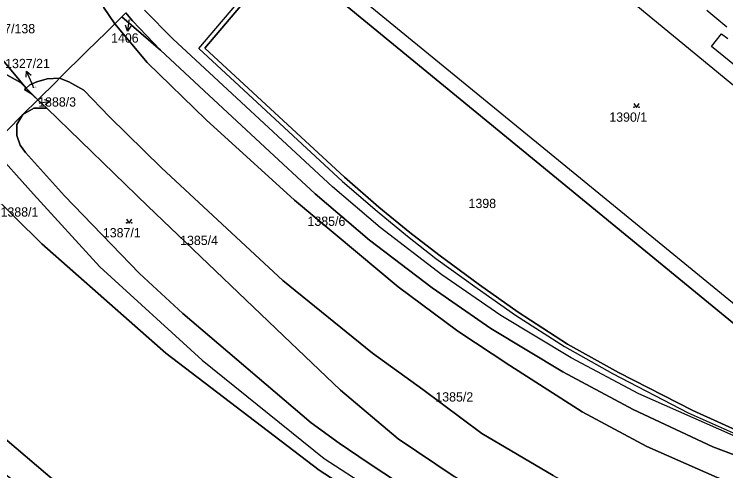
# Model space of a CAD drawing. Extents: x -598934 to -598196, y -1162208 to -1161502.
# Drawn here: x -598686.2 to -598555.4, y -1161981.4 to -1161897.6 of the extents above; entities that cross this region are included whole.
import ezdxf

# ---------------------------------------------------------------- set-up
doc = ezdxf.new("R2010")
doc.units = 0
for name, color, linetype in [('KN_CAR_KR', 7, 'Continuous'), ('KN_KULTURY', 7, 'Continuous'), ('KN_PARC_CIS_POM', 7, 'Continuous'), ('KN_PARC_CIS_POZ', 7, 'Continuous'), ('KN_PARC_PLOCHA', 7, 'Continuous'), ('PARC_C_SIPKA', 7, 'Continuous'), ('parcely_l', 7, 'Continuous')]:
    doc.layers.add(name, color=color, linetype=linetype)

msp = doc.modelspace()

# ---------------------------------------------------------------- linework, layer by layer
at = {"layer": 'KN_CAR_KR'}
for points in [[(-598516.72, -1161941.32), (-598602.99, -1161870.34)], [(-598652.25, -1161903.88), (-598637.61, -1161886.65)], [(-598623.15, -1161894.09), (-598537.06, -1161964.54)], [(-598662.28, -1161896.84), (-598657.06, -1161902.15)], [(-598558.92, -1161896.88), (-598555.23, -1161899.93)], [(-598627.73, -1161929.3), (-598657.06, -1161902.15)], [(-598558.05, -1161903.51), (-598556.19, -1161901.18)], [(-598556.19, -1161901.18), (-598555.07, -1161902.03)], [(-598652.25, -1161903.88), (-598625.88, -1161928.3)], [(-598546.38, -1161912.99), (-598558.05, -1161903.51)], [(-598684, -1161911.17), (-598681.87, -1161913.33)], [(-598682.64, -1161930.66), (-598690.51, -1161921.94)], [(-598625.88, -1161928.3), (-598619.52, -1161933.78)], [(-598618.92, -1161936.73), (-598627.73, -1161929.3)], [(-598682.64, -1161930.66), (-598670.43, -1161944)], [(-598619.52, -1161933.78), (-598613.94, -1161938.33)], [(-598607.61, -1161945.47), (-598618.92, -1161936.73)], [(-598613.94, -1161938.33), (-598608.69, -1161942.42)], [(-598608.69, -1161942.42), (-598601.14, -1161947.88)], [(-598670.43, -1161944), (-598651.65, -1161961.13)], [(-598596.74, -1161952.91), (-598607.61, -1161945.47)], [(-598601.14, -1161947.88), (-598594.08, -1161952.86)], [(-598583.86, -1161960.67), (-598596.74, -1161952.91)], [(-598594.08, -1161952.86), (-598585.08, -1161958.62)], [(-598585.08, -1161958.62), (-598576.24, -1161963.59)], [(-598571.39, -1161967.31), (-598583.86, -1161960.67)], [(-598651.65, -1161961.13), (-598629.22, -1161979.16)], [(-598576.24, -1161963.59), (-598562.32, -1161970.77)], [(-598546.7, -1161978.17), (-598571.39, -1161967.31)], [(-598562.32, -1161970.77), (-598547.47, -1161977.42)], [(-598629.22, -1161979.16), (-598612.23, -1161990.21)]]:
    msp.add_lwpolyline(points, dxfattribs=at)
at = {"layer": 'KN_KULTURY'}
for points in [[(-598572.33, -1161913.97), (-598571.83, -1161914.72), (-598571.33, -1161913.97)], [(-598665.55, -1161935.2), (-598665.05, -1161935.95), (-598664.55, -1161935.2)]]:
    msp.add_lwpolyline(points, dxfattribs=at)
for centre in [(-598572.28, -1161914.67), (-598571.38, -1161914.67), (-598665.5, -1161935.9), (-598664.6, -1161935.9)]:
    msp.add_circle(centre, 0.05, dxfattribs=at)
at = {"layer": 'KN_PARC_PLOCHA'}
for points in [[(-598670.57, -1161893.33), (-598669.8, -1161896.31), (-598667.72, -1161899.35), (-598669.24, -1161900.87), (-598672.85, -1161904.41), (-598677.88, -1161909.36), (-598680.13, -1161909.46), (-598682.02, -1161909.99), (-598683.3, -1161910.59), (-598684, -1161911.17), (-598695.16, -1161897.89), (-598688.82, -1161889.68), (-598683.43, -1161882.7)], [(-598538.52, -1161967.05), (-598636.59, -1161886.64), (-598637.04, -1161887.15), (-598651.19, -1161903.86), (-598625.52, -1161927.53), (-598619.21, -1161933), (-598613.47, -1161937.67), (-598608.15, -1161941.8), (-598600.71, -1161947.3), (-598593.56, -1161952.32), (-598584.52, -1161958.15), (-598575.16, -1161963.39), (-598561.46, -1161970.35), (-598547.04, -1161976.92)], [(-598538.52, -1161967.05), (-598547.04, -1161976.92), (-598561.46, -1161970.35), (-598575.16, -1161963.39), (-598584.52, -1161958.15), (-598593.56, -1161952.32), (-598600.71, -1161947.3), (-598608.15, -1161941.8), (-598613.47, -1161937.67), (-598619.21, -1161933), (-598625.52, -1161927.53), (-598651.19, -1161903.86), (-598637.04, -1161887.15), (-598636.59, -1161886.64)], [(-598684, -1161911.17), (-598685.05, -1161910.11), (-598687.53, -1161908.7), (-598689.32, -1161908.13), (-598691.38, -1161907.92), (-598693.18, -1161908.07), (-598695.22, -1161908.62), (-598696.83, -1161909.36), (-598699, -1161911.05), (-598700.66, -1161912.89), (-598702.8, -1161915.85), (-598703.84, -1161917.32), (-598707.37, -1161913.69), (-598695.16, -1161897.89)], [(-598659.32, -1161904.21), (-598666.41, -1161898.08), (-598665.71, -1161897.32), (-598664.45, -1161898.81)], [(-598684, -1161911.17), (-598684.33, -1161911.44), (-598683.21, -1161912.1), (-598681.87, -1161913.33), (-598684.58, -1161916.02), (-598690.51, -1161921.94), (-598695.11, -1161917.58), (-598694.89, -1161917.09), (-598696.49, -1161916.92), (-598697.85, -1161917.15), (-598699.11, -1161917.76), (-598700.12, -1161918.59), (-598701.26, -1161919.92), (-598703.84, -1161917.32), (-598702.8, -1161915.85), (-598700.66, -1161912.89), (-598699, -1161911.05), (-598696.83, -1161909.36), (-598695.22, -1161908.62), (-598693.18, -1161908.07), (-598691.38, -1161907.92), (-598689.32, -1161908.13), (-598687.53, -1161908.7), (-598685.05, -1161910.11)], [(-598681.87, -1161913.33), (-598683.21, -1161912.1), (-598684.33, -1161911.44), (-598684, -1161911.17), (-598683.3, -1161910.59), (-598682.02, -1161909.99), (-598680.13, -1161909.46), (-598677.88, -1161909.36), (-598678.45, -1161909.95)], [(-598680.2, -1161914.85), (-598682.56, -1161914.86), (-598684.58, -1161916.02), (-598681.87, -1161913.33)]]:
    msp.add_lwpolyline(points, close=True, dxfattribs=at)
for points in [[(-598665.71, -1161897.32), (-598666.41, -1161898.08), (-598667.72, -1161899.35), (-598669.8, -1161896.31)], [(-598544.66, -1161987.36), (-598557.04, -1161982.63), (-598569.93, -1161976.98), (-598581.81, -1161970.58), (-598595.12, -1161962.11), (-598604.67, -1161955.82), (-598615.63, -1161947.65), (-598634.7, -1161931.71), (-598650.91, -1161917.02), (-598661.77, -1161906.44), (-598667.72, -1161899.35), (-598666.41, -1161898.08), (-598659.32, -1161904.21), (-598650.45, -1161912.46), (-598640.12, -1161922.02), (-598630.86, -1161930.55), (-598620.88, -1161939.07), (-598609.4, -1161947.85), (-598598.62, -1161955.32), (-598585.4, -1161963.26), (-598572.47, -1161970.15), (-598557.82, -1161977.02), (-598546.22, -1161981.39)], [(-598546.22, -1161981.39), (-598557.82, -1161977.02), (-598572.47, -1161970.15), (-598585.4, -1161963.26), (-598598.62, -1161955.32), (-598609.4, -1161947.85), (-598620.88, -1161939.07), (-598630.86, -1161930.55), (-598640.12, -1161922.02), (-598650.45, -1161912.46), (-598659.32, -1161904.21), (-598664.45, -1161898.81), (-598665.71, -1161897.32)], [(-598587.17, -1161982.31), (-598600.25, -1161974.56), (-598611.13, -1161966.53), (-598620.32, -1161959.84), (-598636.82, -1161946.48), (-598659.13, -1161925.79), (-598668.67, -1161916.44), (-598673.38, -1161911.52), (-598676.13, -1161910), (-598677.88, -1161909.36), (-598672.85, -1161904.41), (-598669.24, -1161900.87), (-598667.72, -1161899.35), (-598661.77, -1161906.44), (-598650.91, -1161917.02), (-598634.7, -1161931.71), (-598615.63, -1161947.65), (-598604.67, -1161955.82), (-598595.12, -1161962.11), (-598581.81, -1161970.58), (-598569.93, -1161976.98), (-598557.04, -1161982.63)], [(-598605.32, -1161982.49), (-598615.65, -1161975.56), (-598626.22, -1161966.61), (-598636.71, -1161956.62), (-598661.64, -1161932.86), (-598680.2, -1161914.85), (-598681.87, -1161913.33), (-598678.45, -1161909.95), (-598677.88, -1161909.36), (-598676.13, -1161910), (-598673.38, -1161911.52), (-598668.67, -1161916.44), (-598659.13, -1161925.79), (-598636.82, -1161946.48), (-598620.32, -1161959.84), (-598611.13, -1161966.53), (-598600.25, -1161974.56), (-598587.17, -1161982.31)], [(-598615.37, -1161983.78), (-598621.16, -1161979.98), (-598626.47, -1161976.37), (-598631.63, -1161972.6), (-598655.2, -1161952.57), (-598663.14, -1161945.22), (-598676.93, -1161930.93), (-598684.11, -1161923.01), (-598685.09, -1161921.63), (-598685.73, -1161919.84), (-598685.73, -1161917.87), (-598684.58, -1161916.02), (-598682.56, -1161914.86), (-598680.2, -1161914.85), (-598661.64, -1161932.86), (-598636.71, -1161956.62), (-598626.22, -1161966.61), (-598615.65, -1161975.56), (-598605.32, -1161982.49)], [(-598690.51, -1161921.94), (-598684.58, -1161916.02), (-598685.73, -1161917.87), (-598685.73, -1161919.84), (-598685.09, -1161921.63), (-598684.11, -1161923.01), (-598676.93, -1161930.93), (-598663.14, -1161945.22), (-598655.2, -1161952.57), (-598631.63, -1161972.6), (-598626.47, -1161976.37), (-598621.16, -1161979.98), (-598615.37, -1161983.78)], [(-598613.97, -1161991.76), (-598630.16, -1161981.32), (-598658.35, -1161959.86), (-598681.1, -1161939.74), (-598700.98, -1161920.26)], [(-598700.98, -1161920.26), (-598681.1, -1161939.74), (-598658.35, -1161959.86), (-598630.16, -1161981.32), (-598613.97, -1161991.76), (-598595.97, -1162001.6), (-598578.01, -1162010.1), (-598568.51, -1162013.74), (-598559.34, -1162017.25), (-598544.7, -1162021.54), (-598539.94, -1162022.93), (-598510.84, -1162029.39), (-598496.11, -1162031.78), (-598406.5, -1162041.96), (-598368.98, -1162046.88)], [(-598693.35, -1161970.89), (-598667.16, -1161993.18), (-598644.52, -1162009.55), (-598619.13, -1162024.88), (-598591.47, -1162039.7), (-598579.44, -1162044.4), (-598582.71, -1162054.06), (-598588.43, -1162070.55), (-598589.13, -1162070.29), (-598587.08, -1162064.36), (-598586.45, -1162061.72), (-598586.32, -1162059.38), (-598586.65, -1162057.07), (-598587.65, -1162052.06), (-598590.3, -1162047.38), (-598592.24, -1162045.35), (-598595.98, -1162042.57), (-598613.53, -1162032.97), (-598652.95, -1162008.48), (-598673.9, -1161993.31), (-598697.93, -1161974.03)], [(-598370.34, -1162104.09), (-598387.71, -1162097.85), (-598417.86, -1162089.39), (-598437.19, -1162084.14), (-598458.59, -1162078.22), (-598477.74, -1162073.84), (-598530.34, -1162062.11), (-598549.22, -1162055.76), (-598554.19, -1162054.05), (-598555.77, -1162053.54), (-598564.74, -1162050.65), (-598569.94, -1162048.52), (-598571.46, -1162047.71), (-598579.44, -1162044.4), (-598591.47, -1162039.7), (-598619.13, -1162024.88), (-598644.52, -1162009.55), (-598667.16, -1161993.18), (-598693.35, -1161970.89)]]:
    msp.add_lwpolyline(points, dxfattribs=at)
at = {"layer": 'PARC_C_SIPKA'}
for points in [[(-598665.1, -1161898.71), (-598665.37, -1161900.7)], [(-598664.74, -1161899.78), (-598665.37, -1161900.7), (-598665.73, -1161899.64)], [(-598683.97, -1161909.18), (-598683.91, -1161908.06), (-598683.05, -1161908.78)], [(-598682.62, -1161911.09), (-598682.73, -1161910.82), (-598683.91, -1161908.06)], [(-598681.59, -1161913.91), (-598679.61, -1161913.58)], [(-598680.68, -1161913.25), (-598679.61, -1161913.58), (-598680.51, -1161914.24)]]:
    msp.add_lwpolyline(points, dxfattribs=at)
at = {"layer": 'parcely_l'}
for points in [[(-598538.52, -1161967.05), (-598547.04, -1161976.92), (-598561.46, -1161970.35), (-598575.16, -1161963.39), (-598584.52, -1161958.15), (-598593.56, -1161952.32), (-598600.71, -1161947.3), (-598608.15, -1161941.8), (-598613.47, -1161937.67), (-598619.21, -1161933), (-598625.52, -1161927.53), (-598651.19, -1161903.86), (-598637.04, -1161887.15), (-598636.59, -1161886.64), (-598538.52, -1161967.05)], [(-598670.57, -1161893.33), (-598669.8, -1161896.31), (-598667.72, -1161899.35)], [(-598684, -1161911.17), (-598695.16, -1161897.89)], [(-598666.41, -1161898.08), (-598667.72, -1161899.35)], [(-598665.71, -1161897.32), (-598666.41, -1161898.08)], [(-598659.32, -1161904.21), (-598666.41, -1161898.08)], [(-598665.71, -1161897.32), (-598664.45, -1161898.81), (-598659.32, -1161904.21)], [(-598667.72, -1161899.35), (-598669.24, -1161900.87), (-598672.85, -1161904.41), (-598677.88, -1161909.36)], [(-598401.64, -1161997.46), (-598406.14, -1162000.56), (-598412.69, -1162004.16), (-598420.93, -1162007.01), (-598429.78, -1162008.15), (-598434.72, -1162008.36), (-598452.19, -1162006.44), (-598472.89, -1162003.52), (-598492.8, -1162000.75), (-598508.13, -1161998.08), (-598527.93, -1161992.85), (-598544.66, -1161987.36), (-598557.04, -1161982.63), (-598569.93, -1161976.98), (-598581.81, -1161970.58), (-598595.12, -1161962.11), (-598604.67, -1161955.82), (-598615.63, -1161947.65), (-598634.7, -1161931.71), (-598650.91, -1161917.02), (-598661.77, -1161906.44), (-598667.72, -1161899.35)], [(-598502.93, -1161992.35), (-598512.52, -1161990.77), (-598529, -1161987.03), (-598546.22, -1161981.39), (-598557.82, -1161977.02), (-598572.47, -1161970.15), (-598585.4, -1161963.26), (-598598.62, -1161955.32), (-598609.4, -1161947.85), (-598620.88, -1161939.07), (-598630.86, -1161930.55), (-598640.12, -1161922.02), (-598650.45, -1161912.46), (-598659.32, -1161904.21)], [(-598684, -1161911.17), (-598685.05, -1161910.11), (-598687.53, -1161908.7), (-598689.32, -1161908.13), (-598691.38, -1161907.92), (-598693.18, -1161908.07), (-598695.22, -1161908.62), (-598696.83, -1161909.36), (-598699, -1161911.05), (-598700.66, -1161912.89), (-598702.8, -1161915.85), (-598703.84, -1161917.32)], [(-598677.88, -1161909.36), (-598680.13, -1161909.46), (-598682.02, -1161909.99), (-598683.3, -1161910.59), (-598684, -1161911.17)], [(-598681.87, -1161913.33), (-598678.45, -1161909.95), (-598677.88, -1161909.36)], [(-598677.88, -1161909.36), (-598676.13, -1161910), (-598673.38, -1161911.52), (-598668.67, -1161916.44), (-598659.13, -1161925.79), (-598636.82, -1161946.48), (-598620.32, -1161959.84), (-598611.13, -1161966.53), (-598600.25, -1161974.56), (-598587.17, -1161982.31), (-598574.52, -1161989.18), (-598559.72, -1161995.4), (-598545.82, -1162000.39), (-598522.04, -1162008.77)], [(-598681.87, -1161913.33), (-598683.21, -1161912.1), (-598684.33, -1161911.44), (-598684, -1161911.17)], [(-598684.58, -1161916.02), (-598681.87, -1161913.33)], [(-598681.87, -1161913.33), (-598680.2, -1161914.85)], [(-598680.2, -1161914.85), (-598682.56, -1161914.86), (-598684.58, -1161916.02)], [(-598568.43, -1162007.83), (-598568.42, -1162006.87), (-598569.46, -1162003.68), (-598571.13, -1162000.77), (-598575.63, -1161996.89), (-598590.39, -1161991.04), (-598598.04, -1161986.95), (-598605.32, -1161982.49), (-598615.65, -1161975.56), (-598626.22, -1161966.61), (-598636.71, -1161956.62), (-598661.64, -1161932.86), (-598680.2, -1161914.85)], [(-598701.26, -1161919.92), (-598700.12, -1161918.59), (-598699.11, -1161917.76), (-598697.85, -1161917.15), (-598696.49, -1161916.92), (-598694.89, -1161917.09), (-598695.11, -1161917.58), (-598690.51, -1161921.94), (-598684.58, -1161916.02)], [(-598684.58, -1161916.02), (-598685.73, -1161917.87), (-598685.73, -1161919.84), (-598685.09, -1161921.63), (-598684.11, -1161923.01), (-598676.93, -1161930.93), (-598663.14, -1161945.22), (-598655.2, -1161952.57), (-598631.63, -1161972.6), (-598626.47, -1161976.37), (-598621.16, -1161979.98), (-598615.37, -1161983.78), (-598609.31, -1161987.54), (-598603.4, -1161991), (-598596.94, -1161994.49), (-598590.44, -1161998.05), (-598584.75, -1162000.88), (-598579.41, -1162003.28), (-598573.86, -1162005.68), (-598568.43, -1162007.83)], [(-598701.26, -1161919.92), (-598700.98, -1161920.26), (-598681.1, -1161939.74), (-598658.35, -1161959.86), (-598630.16, -1161981.32), (-598613.97, -1161991.76), (-598595.97, -1162001.6), (-598578.01, -1162010.1), (-598568.51, -1162013.74)], [(-598579.44, -1162044.4), (-598591.47, -1162039.7), (-598619.13, -1162024.88), (-598644.52, -1162009.55), (-598667.16, -1161993.18), (-598693.35, -1161970.89), (-598708.28, -1161956.21), (-598714.8, -1161949.33), (-598719.01, -1161944.61)]]:
    msp.add_lwpolyline(points, dxfattribs=at)

# ---------------------------------------------------------------- texts
at = {"layer": 'KN_PARC_CIS_POM'}
for s, p in [('1406', (-598665.27, -1161898.71)), ('1327/21', (-598682.94, -1161911.09)), ('1388/3', (-598681.86, -1161913.91))]:
    msp.add_text(s, height=0.2, dxfattribs=at).set_placement(p)
at = {"layer": 'KN_PARC_CIS_POZ'}
for s, p in [('1327/138', (-598691.83, -1161901.1)), ('1406', (-598668.39, -1161902.81)), ('1327/21', (-598687.86, -1161907.5)), ('1388/3', (-598681.78, -1161914.56)), ('1390/1', (-598576.83, -1161917.34)), ('1398', (-598602.7, -1161933.19)), ('1388/1', (-598688.7, -1161934.76)), ('1385/6', (-598632.29, -1161936.46)), ('1387/1', (-598669.9, -1161938.57)), ('1385/4', (-598655.7, -1161939.97)), ('1385/2', (-598608.8, -1161968.71))]:
    msp.add_text(s, height=1.7, dxfattribs=at).set_placement(p)

doc.saveas('drawing.dxf')
